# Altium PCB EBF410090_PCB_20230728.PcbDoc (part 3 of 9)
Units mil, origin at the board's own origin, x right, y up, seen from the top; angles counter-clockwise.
Board outline 5393.69 x 3858.26 mil, 6 copper layers (TOP, GND02, ART03, ART04, PWR05, BOTTOM), stack 47.2 mil thick; 570 components, 437 nets, 2015 pads, 1260 vias.
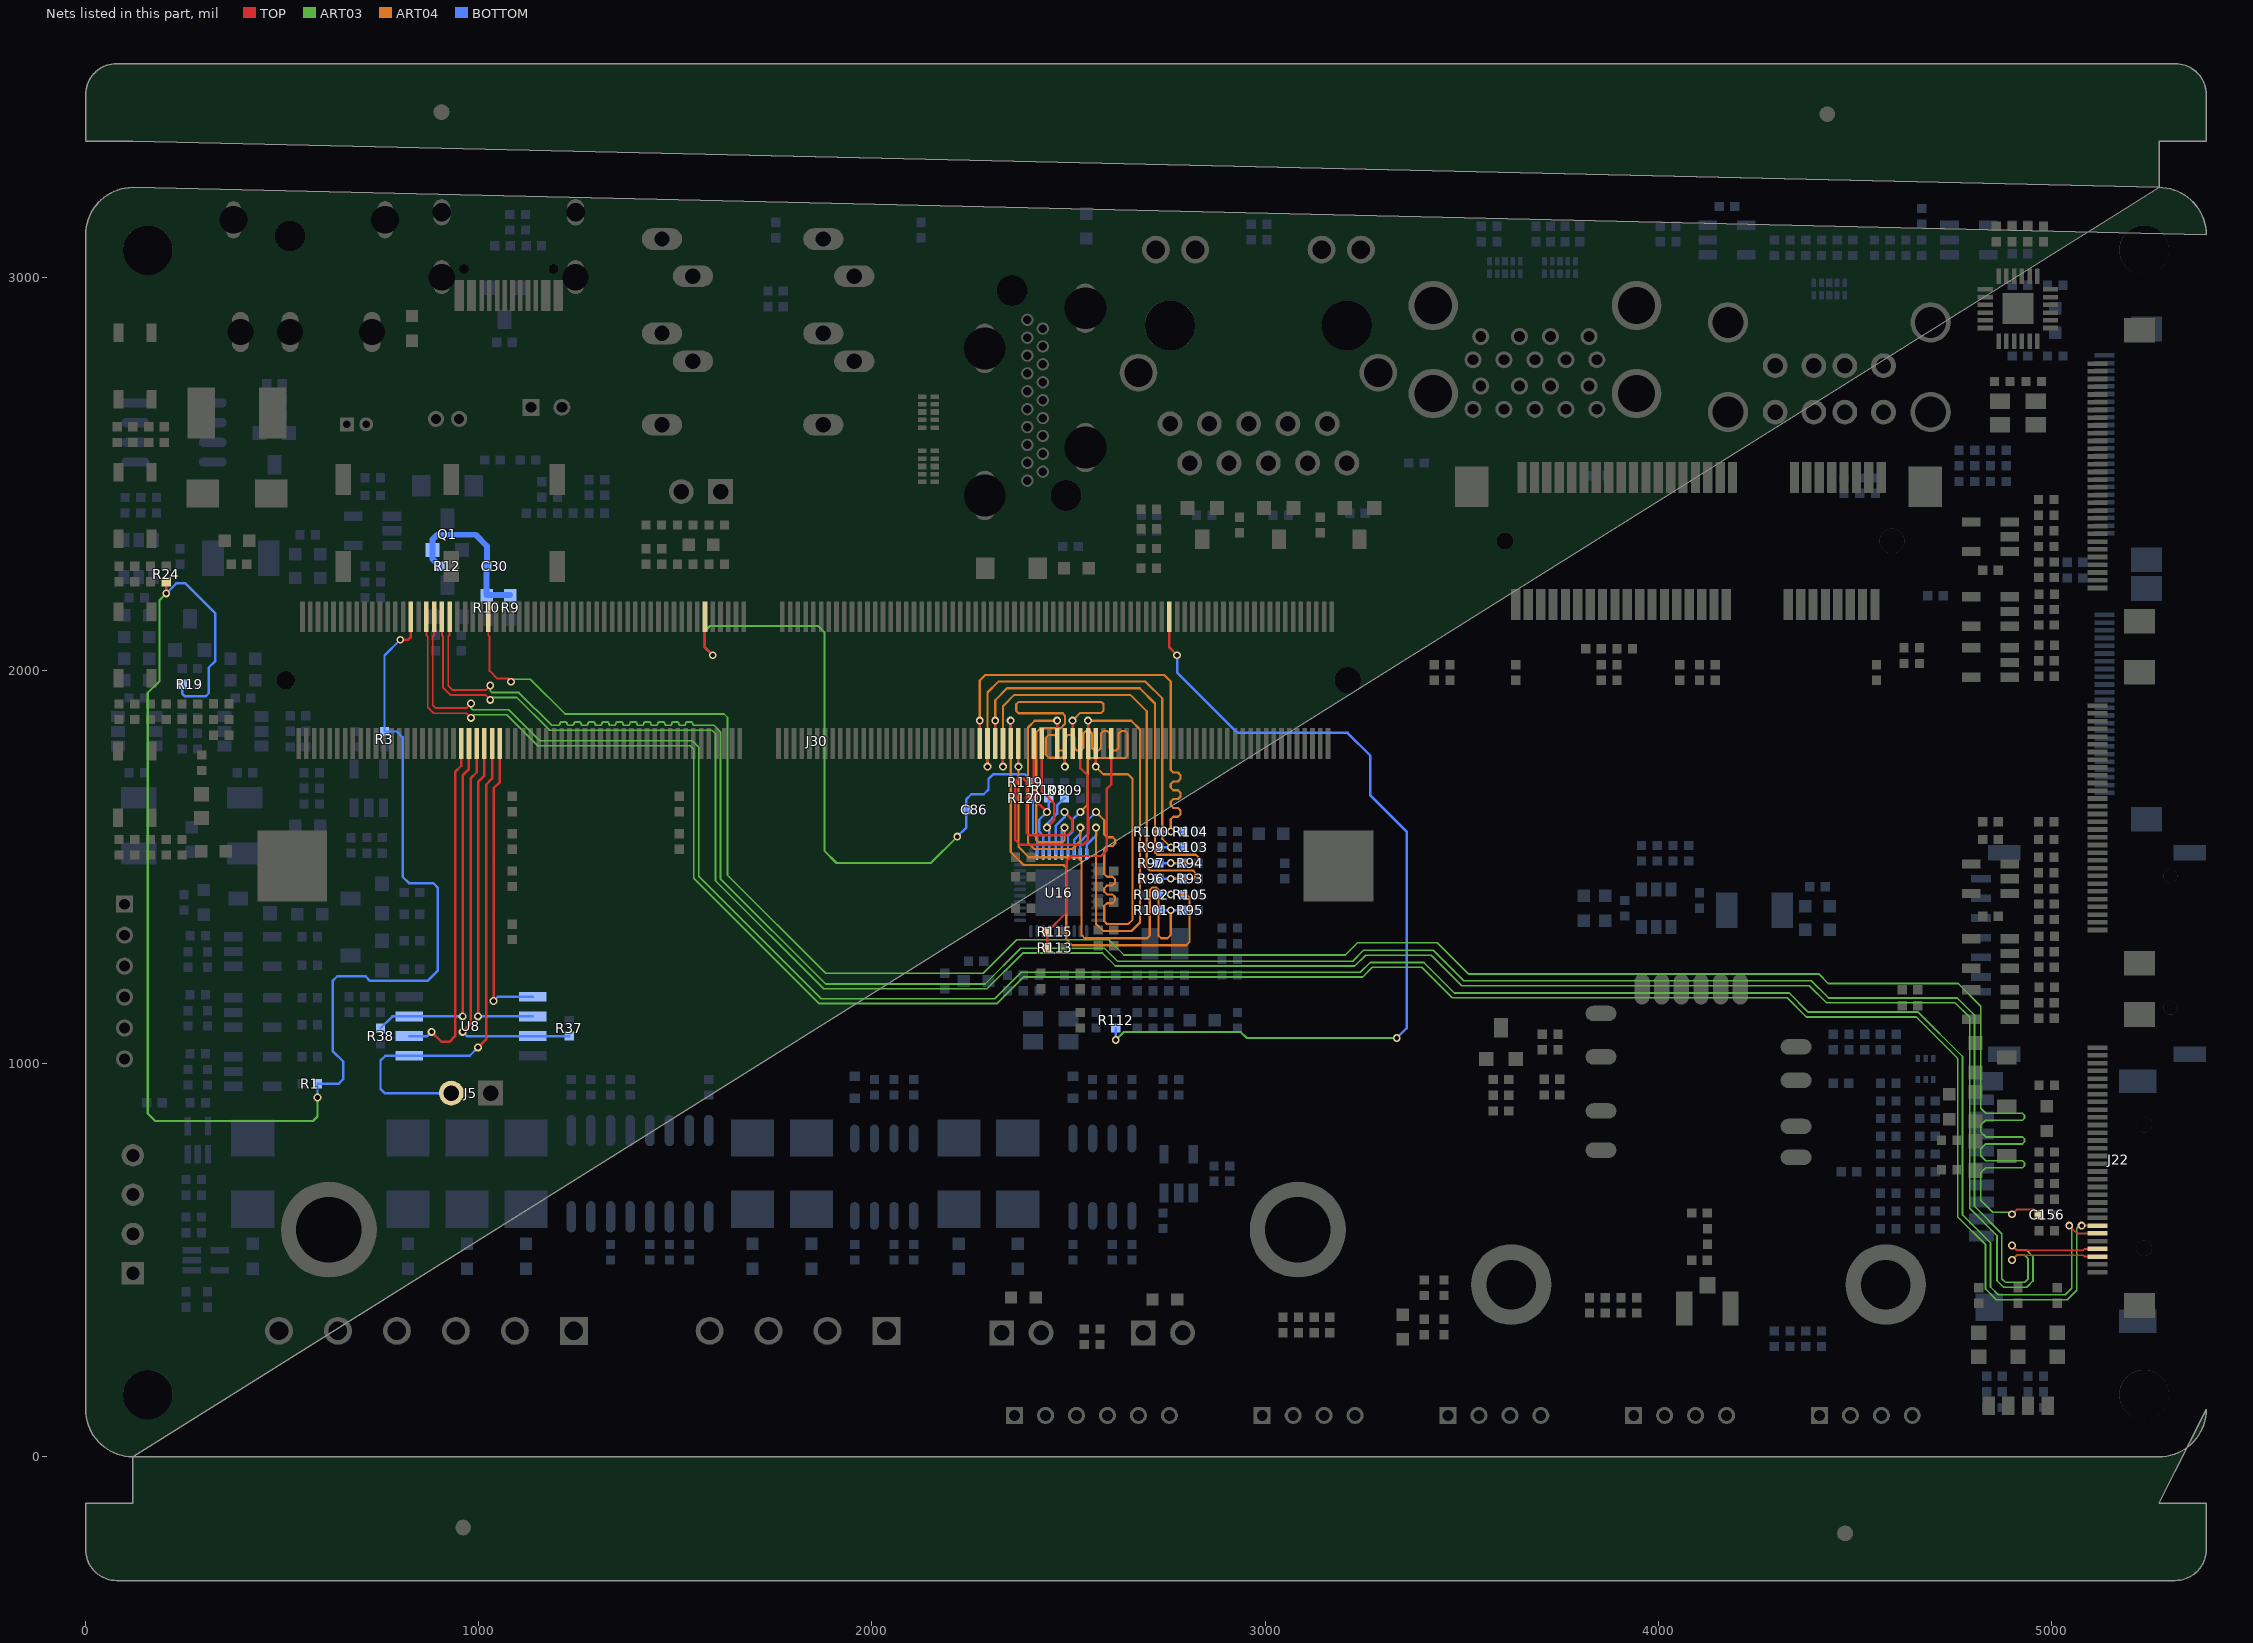
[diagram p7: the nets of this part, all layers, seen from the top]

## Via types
v1: diameter 20, hole 12, TOP to BOTTOM, 1260 vias

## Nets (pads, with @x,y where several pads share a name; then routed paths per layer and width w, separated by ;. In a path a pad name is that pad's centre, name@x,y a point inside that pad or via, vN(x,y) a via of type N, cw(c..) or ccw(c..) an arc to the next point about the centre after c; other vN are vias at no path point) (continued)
EDP_TX_AUXP: C156.1 J30.211 | length 5892
  TOP w4.88: J30.211@1024.09,2136.54 1024.09,2089.67 1027.49,2086.27 1027.49,1998.54 1046.91,1979.12 1074.14,1979.12 v1(1081.95,1971.31) ; v1(4899.64,616.74) 4911.46,628.56 4954.76,628.56 C156.1@4968.32,615
  ART03 w4.44: v1(1081.95,1971.31) 1087.98,1977.34 1131.06,1977.34 1219.4,1889 1623.68,1889 1632.56,1880.12 1632.56,1479.44 1882,1230 2283,1230 2368,1315 2602.4,1315 2641.2,1276.2 3204.2,1276.2 3235,1307 3437.4,1307 3516.4,1228 4408,1228 4432.38,1203.62 4762.78,1203.62 4820.56,1145.84 4820.56,886.34 4833.04,873.86 4926.36,873.86 4931.56,868.66 4931.56,861.3 4926.36,856.1 4833.04,856.1 4820.56,843.62 4820.56,825.94 4833.04,813.46 4926.36,813.46 4931.56,808.26 4931.56,800.9 4926.36,795.7 4833.04,795.7 4820.56,783.22 4820.56,765.54 4833.04,753.06 4926.36,753.06 4931.56,747.86 4931.56,740.5 4926.36,735.3 4833.04,735.3 4820.56,722.82 4820.56,651.85 4850.64,621.77 4894.61,621.77 v1(4899.64,616.74)
EDP_TX_D0N: J22.6 J30.225 | length 5852.8
  TOP w4.88: J30.225@886.3,2136.54 886.3,2089.68 882.89,2086.27 882.89,1911.32 890.21,1904 968.18,1904 v1(980,1915.82) ; v1(5045.39,587.68) 5065.07,568 J22.6@5117.47,568
  ART03 w4.44: v1(980,1915.82) 980,1904.22 984.44,1899.78 1076.22,1899.78 1155,1821 1543.28,1821 1559.44,1804.84 1559.44,1476.56 1871,1165 2312.4,1165 2379.84,1232.44 3242.44,1232.44 3267.12,1257.12 3403.83,1257.12 3481.39,1179.56 4333.43,1179.56 4381.99,1131 4661,1131 4774,1018 4774,615 4845,544 4845,431.6 4864.6,412 5035.4,412 5051.91,428.51 5051.91,581.16 v1(5045.39,587.68)
EDP_TX_D0P: J22.7 J30.227 | length 5851.1
  TOP w4.88: J30.227@866.61,2136.54 866.61,2089.67 870.01,2086.27 870.01,1905.98 884.87,1891.12 968.19,1891.12 v1(980,1879.31) ; v1(5076.88,587.68) J22.7@5117.47,587.68
  ART03 w4.44: v1(980,1879.31) 988.03,1887.34 1071.06,1887.34 1149.84,1808.56 1538.12,1808.56 1547,1799.68 1547,1471.4 1865.84,1152.56 2317.56,1152.56 2385,1220 3247.6,1220 3272.28,1244.68 3398.67,1244.68 3476.23,1167.12 4328.27,1167.12 4376.83,1118.56 4655.84,1118.56 4761.56,1012.84 4761.56,609.84 4832.56,538.84 4832.56,426.44 4859.44,399.56 5040.56,399.56 5064.35,423.35 5064.35,581.35 5070.68,587.68 v1(5076.88,587.68)
EDP_TX_D1N: J22.3 J30.221 | length 5936.4
  TOP w4.88: J30.221@925.67,2136.54 925.67,2089.68 922.26,2086.27 922.26,1960.96 933.34,1949.88 1017.19,1949.88 v1(1029,1961.69) ; v1(4900,500.53) 4911.81,512.34 5080.98,512.34 5084.38,508.94 J22.3@5117.47,508.94
  ART03 w4.44: v1(1029,1961.69) 1029,1948.1 1033.44,1943.66 1101.94,1943.66 1185.16,1860.44 1202.23,1860.44 ccw(c1202.23,1864.72) 1206.51,1864.72 cw(c1210.79,1864.72) 1210.79,1869 1219.99,1869 cw(c1219.99,1864.72) 1224.27,1864.72 ccw(c1228.55,1864.72) 1228.55,1860.44 1237.75,1860.44 ccw(c1237.75,1864.72) 1242.03,1864.72 cw(c1246.31,1864.72) 1246.31,1869 1255.51,1869 cw(c1255.51,1864.72) 1259.79,1864.72 ccw(c1264.07,1864.72) 1264.07,1860.44 1273.27,1860.44 ccw(c1273.27,1864.72) 1277.55,1864.72 cw(c1281.83,1864.72) 1281.83,1869 1291.03,1869 cw(c1291.03,1864.72) 1295.31,1864.72 ccw(c1299.59,1864.72) 1299.59,1860.44 1308.79,1860.44 ccw(c1308.79,1864.72) 1313.07,1864.72 cw(c1317.35,1864.72) 1317.35,1869 1326.55,1869 cw(c1326.55,1864.72) 1330.83,1864.72 ccw(c1335.11,1864.72) 1335.11,1860.44 1344.31,1860.44 ccw(c1344.31,1864.72) 1348.59,1864.72 cw(c1352.87,1864.72) 1352.87,1869 1362.07,1869 cw(c1362.07,1864.72) 1366.35,1864.72 ccw(c1370.63,1864.72) 1370.63,1860.44 1379.83,1860.44 ccw(c1379.83,1864.72) 1384.11,1864.72 cw(c1388.39,1864.72) 1388.39,1869 1397.59,1869 cw(c1397.59,1864.72) 1401.87,1864.72 ccw(c1406.15,1864.72) 1406.15,1860.44 1415.35,1860.44 ccw(c1415.35,1864.72) 1419.63,1864.72 cw(c1423.91,1864.72) 1423.91,1869 1433.11,1869 cw(c1433.11,1864.72) 1437.39,1864.72 ccw(c1441.67,1864.72) 1441.67,1860.44 1450.87,1860.44 ccw(c1450.87,1864.72) 1455.15,1864.72 cw(c1459.43,1864.72) 1459.43,1869 1468.63,1869 cw(c1468.63,1864.72) 1472.91,1864.72 ccw(c1477.19,1864.72) 1477.19,1860.44 1486.39,1860.44 ccw(c1486.39,1864.72) 1490.67,1864.72 cw(c1494.95,1864.72) 1494.95,1869 1504.15,1869 cw(c1504.15,1864.72) 1508.43,1864.72 ccw(c1512.71,1864.72) 1512.71,1860.44 1521.91,1860.44 ccw(c1521.91,1864.72) 1526.19,1864.72 cw(c1530.47,1864.72) 1530.47,1869 1539.67,1869 cw(c1539.67,1864.72) 1543.95,1864.72 ccw(c1548.23,1864.72) 1548.23,1860.44 1598.28,1860.44 1614.44,1844.28 1614.44,1470.56 1882.56,1202.44 2287.44,1202.44 2378.44,1293.44 2591.56,1293.44 2624.46,1260.54 3222.94,1260.54 3250.4,1288 3427.32,1288 3504.88,1210.44 4389.56,1210.44 4433,1167 4760,1167 4804.44,1122.56 4804.44,637.16 4874,567.6 4874,452.6 4883.16,443.44 4931.84,443.44 4940.72,452.32 4940.72,503.68 4931.84,512.56 4912.03,512.56 v1(4900,500.53)
EDP_TX_D1P: J22.4 J30.223 | length 5888.4
  TOP w4.88: J30.223@905.98,2136.54 905.98,2089.67 909.38,2086.27 909.38,1955.62 928,1937 1017.18,1937 v1(1029,1925.18) ; v1(4900,537.04) 4911.82,525.22 5080.98,525.22 5084.39,528.63 J22.4@5117.47,528.63
  ART03 w4.44: v1(1029,1925.18) 1035.04,1931.22 1096.78,1931.22 1180,1848 1593.12,1848 1602,1839.12 1602,1465.4 1877.4,1190 2292.6,1190 2383.6,1281 2586.4,1281 2619.3,1248.1 3228.1,1248.1 3255.56,1275.56 3422.16,1275.56 3499.72,1198 4384.4,1198 4427.84,1154.56 4754.84,1154.56 4792,1117.4 4792,632 4861.56,562.44 4861.56,447.44 4878,431 4937,431 4953.16,447.16 4953.16,508.84 4937,525 4912.04,525 v1(4900,537.04)
EXT_PWR_EN: J30.231 R1.1 R3.1 R19.1 R24.1 | length 4043.6
  TOP w6.16: v1(205,2196) R24.1@205,2225.32 ; v1(800,2078.07) 820.06,2078.07 827.24,2085.25 J30.231@827.24,2136.54
  ART03 w5.61: v1(205,2196) 187.56,2178.56 187.56,1972.56 158,1943 158,873.22 177.22,854 578.46,854 589.68,865.22 v1(589.68,913.42)
  BOTTOM w6.16: v1(205,2196) 230.37,2221.37 253.63,2221.37 330,2145 330,2024 313,2007 313,1942 305,1934 253,1934 245.32,1941.68 R19.1@245.32,1965 ; v1(589.68,913.42) R1.1@589.68,948.42 642.84,948.42 655,960.58 655,1005 628,1032 628,1210 640,1222 712,1222 723.58,1210.42 869.42,1210.42 896,1237 896,1447 884,1459 822,1459 806,1475 806,1830 791.32,1844.68 R3.1@760,1844.68 760,2038.07 v1(800,2078.07)
FAN: C30.1 Q1.2 R9.2 R10.2 R12.1 | length 415.5
  BOTTOM w6.16: C30.1@1020,2264.68 C30.1@1020.32,2265
  BOTTOM w15: R12.1@900.32,2265 882.5,2282.82 Q1.2@882.5,2306.5 882.5,2333.52 893.98,2345 992,2345 1020.32,2316.68 C30.1@1020.32,2265 ; C30.1@1020,2264.68 R10.2@1020,2191.5 R9.2@1080,2191.5
FSPI_CLK: J30.218 U8.6 | length 888.7
  TOP w6.16: v1(880.03,1080.63) 905.66,1055 925,1055 939.69,1069.69 939.69,1741.84 955.19,1757.34 J30.218@955.19,1813.7
  BOTTOM w6.16: U8.6@822.52,1070 869.4,1070 v1(880.03,1080.63)
FSPI_CS0N: J30.208 U8.1 | length 765.4
  TOP w6.16: v1(1037.51,1159.37) 1038.11,1159.97 1038.11,1701.04 1053.61,1716.54 J30.208@1053.61,1813.7
  BOTTOM w6.16: v1(1037.51,1159.37) 1048.14,1170 U8.1@1137.48,1170
FSPI_D0: J5.2 J30.210 U8.5 | length 1306.1
  TOP w6.16: v1(998.14,1041.26) 1018.43,1061.55 1018.43,1709.2 1033.93,1724.7 J30.210@1033.93,1813.7
  BOTTOM w6.16: J5.2@930,925 760,925 750,935 750,1007.68 762.32,1020 U8.5@822.52,1020 976.88,1020 v1(998.14,1041.26)
FSPI_D1: J30.212 U8.2 | length 839.7
  TOP w6.16: v1(998.14,1120) 998.74,1120.6 998.74,1717.36 1014.24,1732.86 J30.212@1014.24,1813.7
  BOTTOM w6.16: v1(998.14,1120) U8.2@1137.48,1120
FSPI_D2: J30.214 R37.2 U8.3 | length 1023.7
  TOP w6.16: v1(958.77,1080.63) 979.06,1100.92 979.06,1725.52 994.56,1741.02 J30.214@994.56,1813.7
  BOTTOM w6.16: v1(958.77,1080.63) 969.4,1070 U8.3@1137.48,1070 1229.68,1070 R37.2@1230,1070.32
FSPI_D3: J30.216 R38.2 U8.7 | length 921.7
  TOP w6.16: v1(958.77,1120) 958.77,1733.08 974.87,1749.18 J30.216@974.87,1813.7
  BOTTOM w6.16: R38.2@750,1089.68 780.32,1120 U8.7@822.52,1120 v1(958.77,1120)
GMAC1_INT: J30.43 R112.1 | length 2255.8
  TOP w6.16: J30.43@2756.37,2136.54 2756.37,2058.37 v1(2776.04,2038.7)
  ART03 w5.61: v1(2620,1060) 2640,1080 2938,1080 2953,1065 v1(3335,1065)
  BOTTOM w6.16: v1(2620,1060) R112.1@2620,1090.32 ; v1(2776.04,2038.7) 2776.04,1994.96 2930,1841 3210,1841 3267.91,1783.09 3267.91,1682.09 3360,1590 3360,1090 v1(3335,1065)
GMAC1_MCLKINOUT_M1: J30.58 R113.1 R115.1 | length 630.6
  TOP w6.16: R113.1@2445.32,1295 R115.1@2445.32,1335 2495.29,1384.97 2495.29,1515.68 2507.61,1528 2583,1528 2597,1542 2597,1697.99 2608.74,1709.73 J30.58@2608.74,1813.7
GMAC1_MDC_M1: J30.78 R108.2 U16.13 | length 344.1
  TOP w6.16: J30.78@2411.89,1813.7 2411.89,1673.11 v1(2445,1640)
  BOTTOM w6.16: U16.13@2435.63,1533.43 2435.63,1579.37 2425,1590 2425,1620 v1(2445,1640) 2450,1645 R108.2@2450,1675.32
GMAC1_MDIO_M1: J30.76 R109.2 U16.14 | length 398.2
  TOP w6.16: J30.76@2431.57,1813.7 2431.57,1693.43 2464.08,1660.92 2464.08,1619.08 v1(2445,1600)
  BOTTOM w6.16: U16.14@2451.38,1533.43 2451.38,1593.62 v1(2445,1600) 2445,1610 2470.92,1635.92 2470.92,1656.24 R109.2@2490,1675.32
GMAC1_RSTN: C86.1 J30.155 R119.2 R120.2 U16.12 | length 1938.1
  TOP w6.16: J30.155@1575.28,2136.54 1575.28,2058.38 v1(1594.96,2038.7)
  ART03 w5.61: v1(1594.96,2038.7) 1574,2059.66 1574,2099 1588,2113 1863,2113 1879,2097 1879,1541 1910,1510 2149.81,1510 v1(2217,1577.19)
  BOTTOM w6.16: v1(2217,1577.19) 2240.32,1600.51 C86.1@2240.32,1645 2240.32,1672.68 2252.64,1685 2284.18,1685 2296.5,1697.32 2296.5,1723.83 2308.82,1736.15 2388.53,1736.15 R119.2@2409.68,1715 R120.2@2409.68,1675 2409.68,1585.32 2420,1575 2420,1533.55 U16.12@2419.88,1533.43
GMAC1_RXCLK_M1: J30.82 R95.2 R101.1 | length 1226.1
  TOP w6.16: v1(2372.52,1755.23) J30.82@2372.52,1813.7
  ART04 w5.61: v1(2372.52,1755.23) 2372.52,1551.48 2399,1525 2522.99,1525 2533,1514.99 2533,1327 2541.14,1318.86 2699.96,1318.86 2706.53,1325.43 2706.53,1441.43 2713.1,1448 2722.4,1448 2728.97,1441.43 2728.97,1325.43 2735.54,1318.86 2751.86,1318.86 2760,1327 v1(2760,1390)
  BOTTOM w6.16: R101.1@2729.68,1390 v1(2760,1390) R95.2@2790.32,1390
GMAC1_RXD0_M1: J30.86 R93.2 R96.1 | length 1268.2
  TOP w6.16: v1(2333.15,1755.23) J30.86@2333.15,1813.7
  ART04 w5.61: v1(2333.15,1755.23) 2333.15,1909.15 2361.82,1937.82 2657.18,1937.82 2699,1896 2699,1498.61 2706.42,1491.19 2816.39,1491.19 2822,1485.58 2822,1475.61 2816.39,1470 v1(2760,1470)
  BOTTOM w6.16: R96.1@2729.68,1470 v1(2760,1470) R93.2@2790.32,1470
GMAC1_RXD1_M1: J30.88 R94.2 R97.1 | length 1182.6
  TOP w6.16: J30.88@2313.46,1813.7 v1(2313.46,1872.17)
  ART04 w5.61: v1(2313.46,1872.17) 2313.46,1924.46 2343.65,1954.65 2681.35,1954.65 2720,1916 2720,1536.61 2725.61,1531 2824.39,1531 2830,1525.39 2830,1515.61 2824.39,1510 v1(2760,1510)
  BOTTOM w6.16: R97.1@2729.68,1510 v1(2760,1510) R94.2@2790.32,1510
GMAC1_RXD2_M1: J30.90 R99.1 R103.1 | length 1169.1
  TOP w6.16: v1(2293.78,1755.23) J30.90@2293.78,1813.7
  ART04 w5.61: v1(2293.78,1755.23) 2293.78,1943.78 2321.48,1971.48 2695.52,1971.48 2738.17,1928.83 2738.17,1571.83 v1(2760,1550)
  BOTTOM w6.16: R99.1@2729.68,1550 v1(2760,1550) R103.1@2790.32,1550
GMAC1_RXD3_M1: J30.92 R100.1 R104.1 | length 1205.4
  TOP w6.16: J30.92@2274.09,1813.7 v1(2274.09,1872.17)
  ART04 w5.61: v1(2274.09,1872.17) 2274.09,1974.1 2288.3,1988.31 2743.69,1988.31 2760,1972 2760,1746.71 2766.57,1740.14 2778.43,1740.14 2785,1733.57 2785,1724.27 2778.43,1717.7 2766.57,1717.7 2760,1711.13 2760,1701.83 2766.57,1695.26 2778.43,1695.26 2785,1688.69 2785,1679.39 2778.43,1672.82 2766.57,1672.82 2760,1666.25 2760,1656.95 2766.57,1650.38 2778.43,1650.38 2785,1643.81 2785,1634.51 2778.43,1627.94 2766.57,1627.94 2760,1621.37 v1(2760,1590)
  BOTTOM w6.16: R100.1@2729.68,1590 v1(2760,1590) R104.1@2790.32,1590
GMAC1_RXDV_CRS_M1: J30.84 R102.1 R105.1 | length 1280
  TOP w6.16: J30.84@2352.83,1813.7 v1(2352.83,1872.17)
  ART04 w5.61: v1(2352.83,1872.17) 2352.83,1538.17 2386,1505 2486.99,1505 2494,1497.99 2494,1316 2509,1301 2799.39,1301 2808,1309.61 2808,1421.39 2799.39,1430 v1(2760,1430)
  BOTTOM w6.16: R102.1@2729.68,1430 v1(2760,1430) R105.1@2790.32,1430
GMAC1_TXCLK_M1: J30.64 U16.20 | length 1141.3
  TOP w6.16: J30.64@2549.68,1813.7 v1(2549.68,1872.17)
  ART04 w5.61: v1(2549.68,1872.17) 2659.78,1872.17 2682,1849.95 2682,1358.62 2660.38,1337 2588,1337 2570,1355 v1(2570,1600)
  BOTTOM w6.16: U16.20@2545.87,1533.43 2545.87,1555.87 2570,1580 v1(2570,1600)
GMAC1_TXD0_M1: J30.72 U16.18 | length 687.5
  TOP w6.16: J30.72@2470.94,1813.7 v1(2470.94,1872.17)
  ART04 w5.61: v1(2470.94,1872.17) 2414.18,1872.17 2397,1854.99 2397,1562 2413,1546 2510,1546 2530,1566 v1(2530,1600)
  BOTTOM w6.16: U16.18@2514.37,1533.43 2514.37,1569.37 2517.96,1572.96 2517.96,1573.17 2530,1585.21 v1(2530,1600)
GMAC1_TXD1_M1: J30.70 U16.17 | length 1116
  TOP w6.16: v1(2490.63,1755.23) J30.70@2490.63,1813.7
  ART04 w5.61: v1(2490.63,1755.23) 2490.63,1772.39 2485.02,1778 2450.01,1778 2442,1786.01 2442,1827.99 2450.01,1836 2463.56,1836 2470.13,1829.43 2470.13,1802.57 2476.7,1796 2486,1796 2492.57,1802.57 2492.57,1829.43 2499.14,1836 2508.44,1836 2515.01,1829.43 2515.01,1802.57 2521.58,1796 2530.88,1796 2537.45,1802.57 2537.45,1839.43 2544.02,1846 2553.32,1846 2559.89,1839.43 2559.89,1802.57 2566.46,1796 2575.76,1796 2582.33,1802.57 2582.33,1839.43 2588.9,1846 2598.2,1846 2604.77,1839.43 2604.77,1802.57 2611.34,1796 2620.64,1796 2627.21,1802.57 2627.21,1839.43 2633.78,1846 2644.39,1846 2650,1840.39 2650,1783 2644,1777 2554.61,1777 2549,1771.39 2549,1659 v1(2530,1640)
  BOTTOM w6.16: U16.17@2498.62,1533.43 2498.62,1578.62 2509.08,1589.08 2509.08,1619.08 v1(2530,1640)
GMAC1_TXD2_M1: J30.68 U16.16 | length 1092.6
  TOP w6.16: J30.68@2510.31,1813.7 v1(2510.31,1872.17)
  ART04 w5.61: v1(2490,1600) 2490,1568.44 2484.39,1562.83 2423.62,1562.83 2418,1568.45 2418,1843 2428,1853 2479.92,1853 2491.14,1864.22 2491.14,1885 2485.14,1891 2372.61,1891 2367,1896.61 2367,1914 2373,1920 2583.39,1920 2589,1914.39 2589,1897.61 2583.39,1892 2530.14,1892 v1(2510.31,1872.17)
  BOTTOM w6.16: U16.16@2482.87,1533.43 2482.87,1592.87 v1(2490,1600)
GMAC1_TXD3_M1: J30.66 U16.15 | length 1055
  TOP w6.16: v1(2490,1640) 2509.08,1620.92 2509.08,1592.09 2497.91,1580.92 2399.58,1580.92 2393.41,1587.09 2393.41,1716.84 2386.25,1724 2371,1724 2364,1717 2364,1569.32 2376.32,1557 2536.76,1557 2549.08,1569.32 2549.08,1731.92 2530,1751 J30.66@2530,1813.7
  BOTTOM w6.16: U16.15@2467.13,1533.43 2467.13,1604.12 2490,1626.99 v1(2490,1640)
GMAC1_TXEN_M1: J30.62 U16.19 | length 1130.1
  TOP w6.16: v1(2569.37,1755.23) J30.62@2569.37,1813.7
  ART04 w5.61: v1(2569.37,1755.23) 2588.6,1736 2651,1736 2663,1724 2663,1366 2652,1355 2598,1355 2591,1362 2591,1401.32 2597.57,1407.89 2611.43,1407.89 2618,1414.46 2618,1423.76 2611.43,1430.33 2597.57,1430.33 2591,1436.9 2591,1446.2 2597.57,1452.77 2611.43,1452.77 2618,1459.34 2618,1468.64 2611.43,1475.21 2597.57,1475.21 2591,1481.78 2591,1546.87 2597.57,1553.44 2612.43,1553.44 2619,1560.01 2619,1569.31 2612.43,1575.88 2597.57,1575.88 2591,1582.45 2591,1619 v1(2570,1640)
  BOTTOM w6.16: U16.19@2530.12,1533.43 2530.12,1565.13 2550,1585.01 2550,1620 v1(2570,1640)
